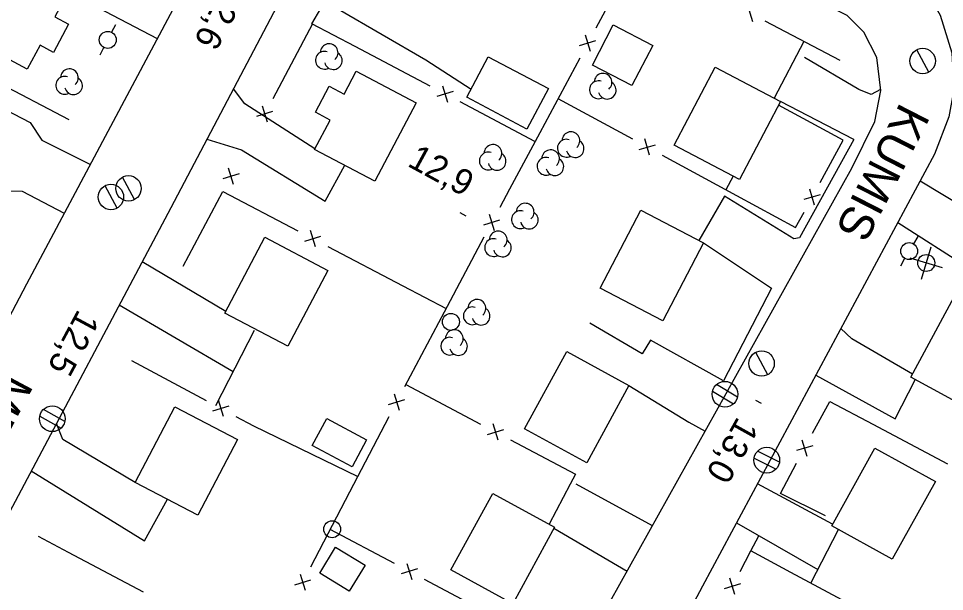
# Model space of a CAD drawing. Extents: x 219136 to 222520, y 5421589 to 5424530.
# Drawn here: x 220473.5 to 220582.8, y 5423523.8 to 5423591.4 of the extents above; entities that cross this region are included whole.
import ezdxf

# ---------------------------------------------------------------- set-up
doc = ezdxf.new("R2010")
doc.units = 0
for name, color, linetype in [('Level 19', 7, 'Continuous'), ('Level 21', 7, 'Continuous'), ('Level 3', 7, 'Continuous'), ('Level 31', 7, 'Continuous'), ('Level 36', 7, 'Continuous'), ('Level 37', 7, 'Continuous'), ('Level 44', 7, 'Continuous')]:
    doc.layers.add(name, color=color, linetype=linetype)

msp = doc.modelspace()

# ---------------------------------------------------------------- linework, layer by layer
at = {"layer": 'Level 19'}
for points in [[(220489.85, 5423589.01), (220479.31, 5423594.55)], [(220505.24, 5423595.29), (220507.99, 5423595.07), (220511.24, 5423592.52), (220521.52, 5423586.51), (220526.88, 5423583.07)], [(220575.22, 5423583.03), (220575.22, 5423583.03), (220574.11, 5423582.42), (220572.64, 5423583.02), (220566.25, 5423586.79)], [(220508.45, 5423576.03), (220500.18, 5423581.35), (220498.83, 5423583.11)], [(220468.95, 5423582.14), (220474.82, 5423579.11), (220476.21, 5423577.04), (220481.95, 5423574.18), (220481.95, 5423574.18)], [(220572.06, 5423577.13), (220563.39, 5423581.61)], [(220495.69, 5423577.14), (220499.77, 5423575.89), (220509.66, 5423569.83), (220511.98, 5423574.07)], [(220588.11, 5423567.23), (220579.88, 5423572.2)], [(220478.87, 5423568.4), (220473.91, 5423570.98), (220468.14, 5423571.07)], [(220564.98, 5423565.39), (220556.78, 5423570.44), (220553.76, 5423565.19)], [(220577.27, 5423567.33), (220585.89, 5423561.82), (220588.61, 5423566.86)], [(220565.64, 5423565.51), (220564.98, 5423565.39)], [(220554.32, 5423564.9), (220562.33, 5423559.58)], [(220497.91, 5423556.83), (220488.05, 5423562.67)], [(220485.35, 5423557.58), (220485.35, 5423557.58), (220498.81, 5423549.73)], [(220556.68, 5423548.61), (220548.08, 5423553.41), (220547.07, 5423551.82), (220540.89, 5423555.42)], [(220578.99, 5423549.43), (220571.82, 5423553.57), (220570.55, 5423554.81)], [(220567.59, 5423549.3), (220576.94, 5423544.13), (220579.32, 5423548.76)], [(220545.52, 5423548.09), (220552.6, 5423543.75), (220554.51, 5423542.67)], [(220487.22, 5423536.64), (220478.67, 5423541.71), (220477.93, 5423543.6)], [(220474.95, 5423537.99), (220488.33, 5423529.74), (220491.02, 5423534.64)], [(220548.3, 5423531.52), (220539.28, 5423536.42)], [(220569.55, 5423531.7), (220560.69, 5423536.45)], [(220536.66, 5423531.24), (220545.3, 5423526.16), (220545.31, 5423526.16)], [(220558.22, 5423531.86), (220567.81, 5423526.33)]]:
    msp.add_lwpolyline(points, dxfattribs=at)
at = {"layer": 'Level 21'}
for points in [[(220443.05, 5423500.35), (220474.45, 5423560.09), (220516.67, 5423639.39), (220546.29, 5423695.15)], [(220554.46, 5423688.81), (220539.92, 5423660.77), (220524.68, 5423632.17), (220524.21, 5423630.58), (220524.06, 5423629.15), (220524.56, 5423627.28), (220525.37, 5423626.07), (220526.84, 5423624.87), (220560.06, 5423607.83), (220573.19, 5423600.82), (220577.54, 5423598.1), (220580.07, 5423595.65), (220582.25, 5423591.8), (220583.62, 5423587.37), (220583.89, 5423583.02), (220583.28, 5423579.78), (220581.6, 5423575.4), (220554.2, 5423524.37), (220519.39, 5423458.76)], [(220571.84, 5423573.74), (220574.53, 5423579.26), (220575.24, 5423582.9), (220574.78, 5423586.8), (220573.23, 5423589.79), (220571.26, 5423591.77), (220544.59, 5423605.36), (220522.28, 5423616.85), (220520.44, 5423617.33), (220518.2, 5423616.92), (220516.46, 5423615.95), (220515.29, 5423614.4), (220491.43, 5423569.04), (220452.59, 5423495.86)], [(220572.06, 5423577.13), (220565.64, 5423565.51)], [(220538.75, 5423514.4), (220571.84, 5423573.74)], [(220562.33, 5423559.58), (220556.68, 5423548.61)]]:
    msp.add_lwpolyline(points, dxfattribs=at)
at = {"layer": 'Level 3'}
for p, q in [((220525.54, 5423568.49), (220526.24, 5423568.11)), ((220560.44, 5423546.35), (220561.14, 5423545.97))]:
    msp.add_line(p, q, dxfattribs=at)
at = {"layer": 'Level 31'}
for points in [[(220467.28, 5423589.27), (220472.14, 5423598.38), (220479.31, 5423594.55), (220477.74, 5423591.61), (220479.37, 5423590.75), (220477.58, 5423587.39), (220475.99, 5423588.24), (220474.49, 5423585.43)], [(220545.87, 5423583.49), (220541.2, 5423585.9), (220543.65, 5423590.65), (220548.32, 5423588.23)], [(220528.9, 5423586.9), (220536.01, 5423583.15), (220533.48, 5423578.35), (220526.37, 5423582.1)], [(220520.41, 5423581.46), (220515.53, 5423572.2), (220508.41, 5423575.95), (220510.24, 5423579.42), (220508.51, 5423580.34), (220510.13, 5423583.42), (220511.9, 5423582.49), (220513.32, 5423585.19)], [(220563.39, 5423581.61), (220558.55, 5423572.41), (220550.84, 5423576.47), (220555.68, 5423585.67)], [(220554.32, 5423564.9), (220549.51, 5423555.7), (220542.12, 5423559.56), (220546.93, 5423568.77)], [(220497.8, 5423556.63), (220502.51, 5423565.58), (220509.96, 5423561.66), (220505.24, 5423552.7)], [(220578.79, 5423549.05), (220583.91, 5423558.55), (220591.09, 5423554.68), (220585.97, 5423545.18)], [(220545.52, 5423548.09), (220540.54, 5423538.95), (220533.2, 5423542.95), (220538.18, 5423552.09)], [(220487.22, 5423536.64), (220491.92, 5423545.57), (220499.31, 5423541.68), (220494.61, 5423532.75)], [(220512.83, 5423538.47), (220508.12, 5423540.98), (220509.83, 5423544.17), (220514.54, 5423541.66)], [(220569.45, 5423531.51), (220574.53, 5423540.68), (220581.69, 5423536.72), (220576.61, 5423527.55)], [(220536.72, 5423531.35), (220531.79, 5423522.31), (220524.5, 5423526.3), (220529.44, 5423535.33)], [(220512.5, 5423523.79), (220509.01, 5423525.92), (220510.87, 5423528.98), (220514.37, 5423526.85)]]:
    msp.add_lwpolyline(points, close=True, dxfattribs=at)
at = {"layer": 'Level 36'}
for p, q in [((220484.9, 5423590.66), (220484.44, 5423589.78)), ((220483.08, 5423587.1), (220483.52, 5423588)), ((220580.91, 5423585.06), (220579.49, 5423587.7)), ((220487.15, 5423570.02), (220485.73, 5423572.66)), ((220485.08, 5423569), (220483.66, 5423571.64)), ((220579.62, 5423565.67), (220579.11, 5423564.81)), ((220580.04, 5423560.62), (220581.19, 5423564.44)), ((220577.6, 5423562.21), (220578.09, 5423563.09)), ((220582.53, 5423561.96), (220578.71, 5423563.11)), ((220561.9, 5423549.34), (220560.48, 5423551.98)), ((220558.32, 5423546.68), (220555.85, 5423548.21)), ((220555.38, 5423547.42), (220557.85, 5423545.89)), ((220475.96, 5423544.44), (220478.49, 5423543.03)), ((220478.92, 5423543.84), (220476.39, 5423545.25)), ((220563.28, 5423539.02), (220560.69, 5423540.31)), ((220560.3, 5423539.48), (220562.89, 5423538.19))]:
    msp.add_line(p, q, dxfattribs=at)
for centre, radius in [((220483.98, 5423588.88), 1), ((220580.19, 5423586.39), 1.5), ((220486.43, 5423571.35), 1.5), ((220484.36, 5423570.33), 1.5), ((220578.6, 5423563.94), 1), ((220580.62, 5423562.54), 1), ((220524.5, 5423555.58), 1), ((220561.18, 5423550.67), 1.5), ((220556.85, 5423547.04), 1.52), ((220477.44, 5423544.15), 1.52), ((220561.79, 5423539.26), 1.52), ((220510.48, 5423531.1), 1)]:
    msp.add_circle(centre, radius, dxfattribs=at)
at = {"layer": 'Level 37'}
for p, q in [((220559.51, 5423592.97), (220560.11, 5423591.06)), ((220540.35, 5423589.46), (220540.93, 5423587.54)), ((220539.69, 5423588.21), (220541.6, 5423588.79)), ((220524.76, 5423582.78), (220522.85, 5423582.19)), ((220523.51, 5423583.45), (220524.1, 5423581.53)), ((220501.57, 5423579.86), (220503.49, 5423580.45)), ((220502.23, 5423581.11), (220502.82, 5423579.2)), ((220547.96, 5423575.27), (220547.39, 5423577.19)), ((220546.72, 5423575.94), (220548.64, 5423576.51)), ((220498.82, 5423571.8), (220498.24, 5423573.72)), ((220499.49, 5423573.05), (220497.57, 5423572.47)), ((220568.11, 5423570.59), (220566.18, 5423570.03)), ((220567.43, 5423569.35), (220566.86, 5423571.27)), ((220529.03, 5423568.29), (220529.62, 5423566.38)), ((220528.37, 5423567.04), (220530.29, 5423567.63)), ((220508.51, 5423564.46), (220507.91, 5423566.37)), ((220507.25, 5423565.12), (220509.16, 5423565.71)), ((220517.12, 5423545.84), (220519.04, 5423546.43)), ((220517.79, 5423547.09), (220518.37, 5423545.18)), ((220496.39, 5423545.09), (220498.31, 5423545.67)), ((220497.64, 5423544.42), (220497.06, 5423546.33)), ((220530.07, 5423541.63), (220529.48, 5423543.54)), ((220528.82, 5423542.29), (220530.73, 5423542.88)), ((220567.22, 5423540.96), (220565.3, 5423540.38)), ((220566.55, 5423539.71), (220565.97, 5423541.63)), ((220519.3, 5423527.07), (220519.88, 5423525.16)), ((220506.71, 5423525.8), (220507.31, 5423523.89)), ((220520.55, 5423526.41), (220518.63, 5423525.82)), ((220506.06, 5423524.54), (220507.97, 5423525.14)), ((220558.67, 5423524.66), (220556.76, 5423524.06)), ((220558.01, 5423523.4), (220557.42, 5423525.32))]:
    msp.add_line(p, q, dxfattribs=at)
for points in [[(220546.31, 5423599.08), (220541.59, 5423590.26)], [(220513.19, 5423588.09), (220508.09, 5423590.78), (220509.13, 5423592.58)], [(220508.14, 5423590.76), (220503.46, 5423581.92)], [(220570.44, 5423586.45), (220561.58, 5423591.09)], [(220522.04, 5423583.42), (220513.19, 5423588.09)], [(220566.17, 5423588.68), (220562.66, 5423582)], [(220539.7, 5423586.74), (220534.98, 5423577.92)], [(220479.41, 5423579.44), (220470.55, 5423584.08)], [(220534.42, 5423576.89), (220525.58, 5423581.56)], [(220537.13, 5423581.95), (220545.92, 5423577.18)], [(220567.01, 5423579.1), (220563.16, 5423581.17)], [(220568.1, 5423572.06), (220570.82, 5423577.04), (220567.01, 5423579.1)], [(220534.98, 5423577.92), (220531.41, 5423571.26), (220530.27, 5423569.1)], [(220549.44, 5423575.27), (220558.23, 5423570.51)], [(220557.81, 5423572.8), (220556.97, 5423571.19)], [(220492.87, 5423562.18), (220497.59, 5423571)], [(220497.58, 5423570.99), (220506.44, 5423566.35)], [(220558.23, 5423570.51), (220565.19, 5423566.73), (220566.19, 5423568.55)], [(220528.39, 5423565.57), (220523.7, 5423556.74)], [(220509.98, 5423564.49), (220518.83, 5423559.84)], [(220518.83, 5423559.84), (220523.93, 5423557.17)], [(220523.7, 5423556.74), (220519.02, 5423547.9)], [(220496.75, 5423545.7), (220501.3, 5423554.6)], [(220486.77, 5423551.04), (220495.59, 5423546.32)], [(220519.17, 5423548.2), (220528.01, 5423543.52)], [(220567.2, 5423542.43), (220569.22, 5423546.19), (220574.29, 5423543.5)], [(220499.11, 5423544.43), (220501.21, 5423543.31), (220508.06, 5423539.97)], [(220517.15, 5423544.37), (220512.54, 5423535.49)], [(220574.29, 5423543.5), (220583.12, 5423538.81)], [(220531.54, 5423541.65), (220539.19, 5423537.6), (220538.56, 5423536.41)], [(220508.06, 5423539.97), (220513.49, 5423537.32)], [(220568.71, 5423532.69), (220563.39, 5423535.33), (220565.31, 5423538.91)], [(220512.54, 5423535.49), (220507.93, 5423526.62)], [(220538.56, 5423536.41), (220536.09, 5423531.7)], [(220517.83, 5423527.06), (220510.26, 5423531.09)], [(220479.36, 5423528.35), (220475.81, 5423530.23)], [(220558.65, 5423526.13), (220559.92, 5423528.54), (220560.87, 5423530.33)], [(220566.99, 5423524.74), (220570.25, 5423531.07)], [(220488.2, 5423523.67), (220479.36, 5423528.35)], [(220564.63, 5423526.01), (220559.92, 5423528.54)], [(220573.44, 5423521.28), (220564.63, 5423526.01)], [(220530.18, 5423520.47), (220521.36, 5423525.17)]]:
    msp.add_lwpolyline(points, dxfattribs=at)
at = {"layer": 'Level 44'}
for centre, start, end in [((220510.12, 5423587.37), 310.1588, 177.6158), ((220509.57, 5423586.48), 72.005, 297.6935), ((220510.61, 5423586.44), 194.8265, 57.5108), ((220479.46, 5423584.41), 310.1588, 177.6158), ((220542.46, 5423583.88), 310.1588, 177.6158), ((220478.91, 5423583.52), 72.005, 297.6935), ((220479.95, 5423583.48), 194.8265, 57.5108), ((220541.91, 5423582.99), 72.005, 297.6935), ((220542.95, 5423582.95), 194.8265, 57.5108), ((220538.12, 5423576.09), 72.005, 297.6935), ((220538.67, 5423576.98), 310.1588, 177.6158), ((220529.46, 5423575.47), 310.1588, 177.6158), ((220536.27, 5423574.85), 310.1588, 177.6158), ((220539.16, 5423576.05), 194.8265, 57.5108), ((220528.91, 5423574.58), 72.005, 297.6935), ((220529.95, 5423574.54), 194.8265, 57.5108), ((220535.72, 5423573.96), 72.005, 297.6935), ((220536.76, 5423573.92), 194.8265, 57.5108), ((220533.26, 5423568.54), 310.1588, 177.6158), ((220532.71, 5423567.65), 72.005, 297.6935), ((220533.75, 5423567.61), 194.8265, 57.5108), ((220530.08, 5423565.25), 310.1588, 177.6158), ((220529.53, 5423564.36), 72.005, 297.6935), ((220530.57, 5423564.32), 194.8265, 57.5108), ((220527.02, 5423556.3), 72.005, 297.6935), ((220527.57, 5423557.19), 310.1588, 177.6158), ((220528.06, 5423556.26), 194.8265, 57.5108), ((220524.9, 5423553.61), 310.1588, 177.6158), ((220524.35, 5423552.72), 72.005, 297.6935), ((220525.39, 5423552.68), 194.8265, 57.5108)]:
    msp.add_arc(centre, 1.05, start, end, dxfattribs=at)

# ---------------------------------------------------------------- texts
at = {"layer": 'Level 21'}
for s, rotation, p in [('KUMIS', 242.8834, (220577.58, 5423581.63)), ('MESSEK', 241.9688, (220471.75, 5423549.91))]:
    msp.add_text(s, height=4, rotation=rotation, dxfattribs=at).set_placement(p)
at = {"layer": 'Level 3'}
for s, rotation, p in [('12,6', 241.9194, (220497.79, 5423595.72)), ('12,9', 331.383, (220519.24, 5423574.05)), ('12,5', 241.7829, (220480.5, 5423557.18)), ('13,0', 240.8145, (220558.35, 5423544.51))]:
    msp.add_text(s, height=3, rotation=rotation, dxfattribs=at).set_placement(p)

doc.saveas('drawing.dxf')
